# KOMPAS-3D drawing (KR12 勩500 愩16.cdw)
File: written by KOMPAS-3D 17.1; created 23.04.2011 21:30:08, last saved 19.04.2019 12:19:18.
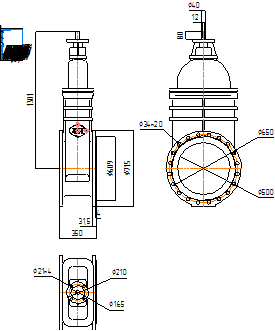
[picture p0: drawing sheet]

Sheet 1: A4, portrait

Title block, sheet 1: name: KR12 Ду500 Ру16; material: Внимание! Данный продукт является объектом авторского права ООО «Торговый Дом АДЛ». / Запрещается изменение, копирование, распространение / (в том числе путем копирования на другие сайты и ресурсы в Интернете) / или любое иное использование информации и объектов без предварительного / согласия правообладателя (ООО «Торговый Дом АДЛ»).; scale: 1:1; sheets: 1; organisation: ООО "Торговый дом АДЛ"; sheet format: A4; stored path: \\adlc.lan\data\АДЛ_ПКД\3D-модели\ADL production\Клиновые задвижки серии KR ГРАНАР\Клиновые задвижки KR12\KOMPAS 2D\KR12 Ду500 Ру16.cdw

Views: Спереди 4, Проекционный вид 5, Проекционный вид 6
Dimensions and other numbers on the sheet: 350; 609; 715; 1301; 4; 31,5; 210; 21; 165; 12; 80; 650; 500; 34; 40; 1:1; 1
